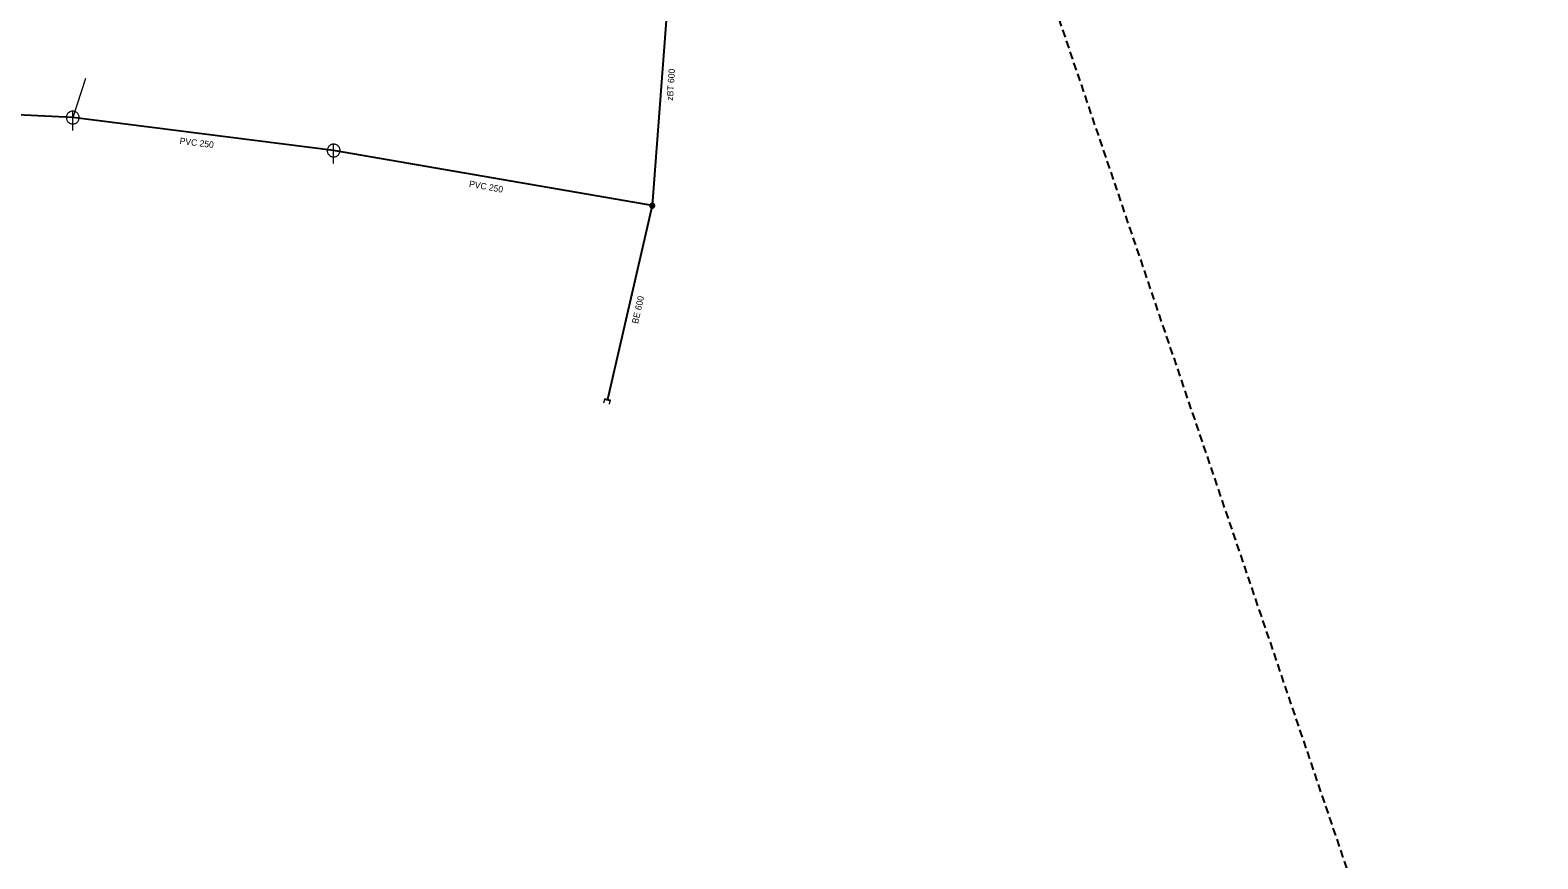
# Model space of a CAD drawing. Extents: x -659250 to -657316, y -997555 to -993684.
# Drawn here: x -658279.6 to -658044.4, y -995254.3 to -995125.1 of the extents above; entities that cross this region are included whole.
import ezdxf

# ---------------------------------------------------------------- set-up
doc = ezdxf.new("R2010")
doc.units = 0
doc.header["$LTSCALE"] = 0.4
doc.linetypes.add('MEDIUM_DASHED', pattern=[4.5, 3, -1.5])
doc.layers.add('1', color=7, linetype='Continuous')
for name, color, linetype, lineweight in [('11', 7, 'Continuous', 13), ('14', 7, 'Continuous', 25), ('22', 7, 'Continuous', 13), ('29', 7, 'Continuous', 13), ('63', 7, 'MEDIUM_DASHED', 25)]:
    doc.layers.add(name, color=color, linetype=linetype, lineweight=lineweight)

msp = doc.modelspace()

# ---------------------------------------------------------------- linework, layer by layer
at = {"layer": '11'}
msp.add_line((-658270.95, -995132.64), (-658272.95, -995138.75), dxfattribs=at)
at = {"layer": '14'}
for p, q in [((-658272.949, -995138.75), (-658295.55, -995137.62)), ((-658182.53, -995152.469), (-658189.53, -995182.699))]:
    msp.add_line(p, q, dxfattribs=at)
msp.add_lwpolyline([(-658175.079, -995105.37), (-658179.557, -995112.526), (-658182.53, -995152.469), (-658232.25, -995143.89), (-658272.949, -995138.75)], dxfattribs=at)
at = {"layer": '22'}
for p, q in [((-658272.95, -995140.75), (-658272.949, -995137.75)), ((-658232.25, -995145.89), (-658232.249, -995142.89))]:
    msp.add_line(p, q, dxfattribs=at)
for points in [[(-658271.95, -995138.75), (-658271.955, -995138.641), (-658271.973, -995138.533), (-658272.003, -995138.427), (-658272.043, -995138.326), (-658272.095, -995138.229), (-658272.157, -995138.139), (-658272.229, -995138.056), (-658272.309, -995137.982), (-658272.397, -995137.916), (-658272.491, -995137.861), (-658272.591, -995137.816), (-658272.696, -995137.783), (-658272.803, -995137.761), (-658272.912, -995137.751), (-658273.022, -995137.753), (-658273.13, -995137.767), (-658273.237, -995137.792), (-658273.34, -995137.829), (-658273.438, -995137.878), (-658273.53, -995137.936), (-658273.616, -995138.005), (-658273.693, -995138.082), (-658273.762, -995138.168), (-658273.821, -995138.26), (-658273.869, -995138.358), (-658273.906, -995138.461), (-658273.932, -995138.568), (-658273.946, -995138.676), (-658273.949, -995138.786), (-658273.939, -995138.895), (-658273.918, -995139.002), (-658273.884, -995139.106), (-658273.84, -995139.206), (-658273.785, -995139.301), (-658273.719, -995139.389), (-658273.645, -995139.469), (-658273.562, -995139.541), (-658273.472, -995139.603), (-658273.376, -995139.655), (-658273.274, -995139.696), (-658273.169, -995139.726), (-658273.061, -995139.744), (-658272.951, -995139.75), (-658272.842, -995139.744), (-658272.734, -995139.726), (-658272.629, -995139.697), (-658272.527, -995139.656), (-658272.43, -995139.604), (-658272.34, -995139.542), (-658272.257, -995139.471), (-658272.182, -995139.391), (-658272.117, -995139.303), (-658272.061, -995139.209), (-658272.017, -995139.109), (-658271.983, -995139.005), (-658271.961, -995138.897), (-658271.951, -995138.788)], [(-658231.25, -995143.89), (-658231.255, -995143.781), (-658231.273, -995143.673), (-658231.303, -995143.567), (-658231.343, -995143.466), (-658231.395, -995143.369), (-658231.457, -995143.279), (-658231.529, -995143.196), (-658231.609, -995143.122), (-658231.697, -995143.056), (-658231.791, -995143.001), (-658231.891, -995142.956), (-658231.996, -995142.923), (-658232.103, -995142.901), (-658232.212, -995142.891), (-658232.322, -995142.893), (-658232.43, -995142.907), (-658232.537, -995142.932), (-658232.64, -995142.969), (-658232.738, -995143.018), (-658232.83, -995143.076), (-658232.916, -995143.145), (-658232.993, -995143.222), (-658233.062, -995143.308), (-658233.121, -995143.4), (-658233.169, -995143.498), (-658233.206, -995143.601), (-658233.232, -995143.708), (-658233.246, -995143.816), (-658233.249, -995143.926), (-658233.239, -995144.035), (-658233.218, -995144.142), (-658233.184, -995144.246), (-658233.14, -995144.346), (-658233.085, -995144.441), (-658233.019, -995144.529), (-658232.945, -995144.609), (-658232.862, -995144.681), (-658232.772, -995144.743), (-658232.676, -995144.795), (-658232.574, -995144.836), (-658232.469, -995144.866), (-658232.361, -995144.884), (-658232.251, -995144.89), (-658232.142, -995144.884), (-658232.034, -995144.866), (-658231.929, -995144.837), (-658231.827, -995144.796), (-658231.73, -995144.744), (-658231.64, -995144.682), (-658231.557, -995144.611), (-658231.482, -995144.531), (-658231.417, -995144.443), (-658231.361, -995144.349), (-658231.317, -995144.249), (-658231.283, -995144.145), (-658231.261, -995144.037), (-658231.251, -995143.928)], [(-658182.139, -995152.473), (-658182.145, -995152.405), (-658182.163, -995152.338), (-658182.192, -995152.276), (-658182.232, -995152.219), (-658182.28, -995152.171), (-658182.337, -995152.131), (-658182.399, -995152.102), (-658182.465, -995152.084), (-658182.534, -995152.077), (-658182.603, -995152.083), (-658182.669, -995152.101), (-658182.732, -995152.129), (-658182.788, -995152.169), (-658182.837, -995152.217), (-658182.877, -995152.273), (-658182.907, -995152.335), (-658182.925, -995152.402), (-658182.932, -995152.47), (-658182.926, -995152.539), (-658182.909, -995152.606), (-658182.88, -995152.668), (-658182.841, -995152.725), (-658182.793, -995152.774), (-658182.737, -995152.814), (-658182.675, -995152.844), (-658182.609, -995152.863), (-658182.54, -995152.87), (-658182.471, -995152.864), (-658182.405, -995152.847), (-658182.342, -995152.819), (-658182.285, -995152.78), (-658182.236, -995152.732), (-658182.195, -995152.676), (-658182.165, -995152.614), (-658182.147, -995152.548), (-658182.139, -995152.48)], [(-658182.525, -995152.775), (-658182.488, -995152.768), (-658182.453, -995152.75), (-658182.421, -995152.721), (-658182.393, -995152.682), (-658182.371, -995152.635), (-658182.355, -995152.582), (-658182.346, -995152.525), (-658182.345, -995152.465), (-658182.351, -995152.406), (-658182.364, -995152.351), (-658182.383, -995152.3), (-658182.409, -995152.257), (-658182.439, -995152.223), (-658182.473, -995152.199), (-658182.509, -995152.187), (-658182.546, -995152.186), (-658182.582, -995152.198), (-658182.616, -995152.22), (-658182.647, -995152.254), (-658182.672, -995152.296), (-658182.692, -995152.347), (-658182.705, -995152.402), (-658182.71, -995152.461), (-658182.709, -995152.52), (-658182.7, -995152.578), (-658182.684, -995152.631), (-658182.661, -995152.679), (-658182.634, -995152.719), (-658182.602, -995152.748), (-658182.567, -995152.767), (-658182.53, -995152.775)]]:
    msp.add_lwpolyline(points, close=True, dxfattribs=at)
at = {"layer": '29'}
for points in [[(-658189.184, -995183.415), (-658189.046, -995182.81), (-658190.013, -995182.588), (-658190.152, -995183.195)], [(-658190.067, -995183.214), (-658189.948, -995182.692), (-658189.151, -995182.875), (-658189.27, -995183.396)]]:
    msp.add_lwpolyline(points, dxfattribs=at)
at = {"layer": '63'}
msp.add_lwpolyline([(-659116.685, -993855.266), (-658551.464, -993848.288), (-658551.464, -993848.288), (-657316.352, -997490.822), (-657316.352, -997490.822), (-657839.705, -997490.822), (-657839.705, -997490.822)], close=True, dxfattribs=at)

# ---------------------------------------------------------------- texts
at = {"layer": '1'}
for s, rotation, p in [('zBT 600 ', 86, (-658179.323, -995136.135)), ('PVC 250 ', 353, (-658256.321, -995142.85)), ('PVC 250 ', 350, (-658211.176, -995149.54)), ('BE 600', 77, (-658184.771, -995170.954))]:
    msp.add_text(s, height=1, rotation=rotation, dxfattribs=at).set_placement(p)

doc.saveas('drawing.dxf')
